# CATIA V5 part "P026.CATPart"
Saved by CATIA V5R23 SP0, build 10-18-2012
Part number: 05-LICP-T02-E-S05-P026
Definition: Rondelle ressort Ø 8.2
Description: Rondelle ressort Ø 8.2
Property "SUPPLIER": "NORELEM"
Property "REFERENCE": "NLM 07360-080"
Property "MATERIAL": "Acier à ressort"
Property "AUTHOR": "Trace Parts S.A."
Property "WEB": "www.traceparts.com"
Bounding box of the stored display mesh (mm): x -7.974 to 7.974, y -7.998 to 7.998, z 0 to 1.25
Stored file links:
  C:\wamp\www\COURS\CONCEPTION GMP1\TITRE 02-SEMESTRE 2\03-TP7-PRESSE MECANIQUE\eleve\P026.CATPart
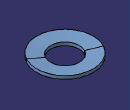
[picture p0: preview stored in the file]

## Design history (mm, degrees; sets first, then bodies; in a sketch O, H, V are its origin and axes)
Set1
  Plane1: type Offset, RefPlane xy-plane, Offset 1.25
Body1 (main body)
  Solid1: solid without history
